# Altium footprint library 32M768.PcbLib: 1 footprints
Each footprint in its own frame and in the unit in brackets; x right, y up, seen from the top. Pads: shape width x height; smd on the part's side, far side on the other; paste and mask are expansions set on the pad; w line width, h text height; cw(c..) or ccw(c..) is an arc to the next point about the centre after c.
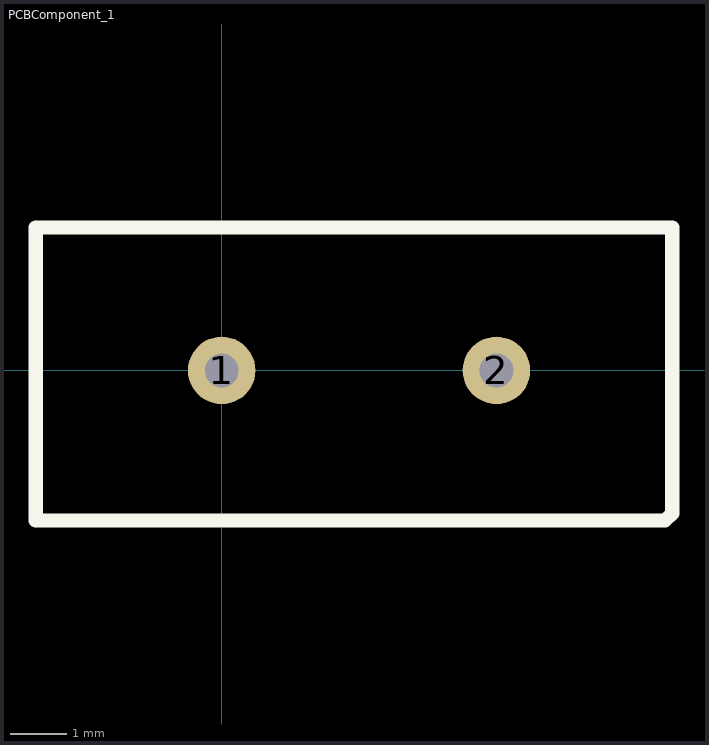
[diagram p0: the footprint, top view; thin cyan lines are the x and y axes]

## PCBComponent_1 [mm]
pads (2):
  round 1.2 hole 0.6: 1(0,0) 2(4.88,0)
Top Overlay:
  lines w0.254: -3.302,-2.667 7.874,-2.667 8.001,-2.54 8.001,2.54 -3.302,2.54 -3.302,0 -3.302,-2.667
